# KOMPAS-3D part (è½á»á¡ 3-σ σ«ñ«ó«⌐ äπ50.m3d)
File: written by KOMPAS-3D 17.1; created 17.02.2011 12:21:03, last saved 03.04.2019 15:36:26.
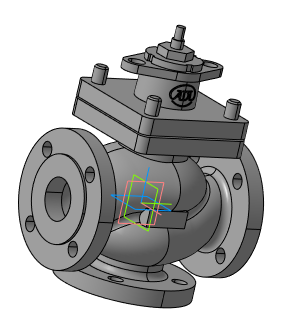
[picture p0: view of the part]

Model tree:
1. Плоскость XY
2. Плоскость ZX
3. Плоскость ZY
4. Ось X
5. Ось Y
6. Ось Z
7. Начало координат
8. Операция без истории:3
